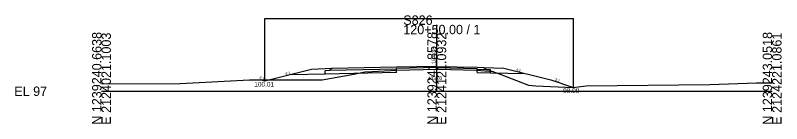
# Model space of a CAD drawing. Extents: x 2119282 to 2119710, y 1215030 to 1220057.
# Drawn here: x 2119381.9 to 2119610.4, y 1219030.1 to 1219062.5 of the extents above; entities that cross this region are included whole.
import ezdxf

# ---------------------------------------------------------------- set-up
doc = ezdxf.new("R2010")
doc.units = 0
for name, color, linetype in [('XS_CELL', 7, 'Continuous'), ('XS_M_DITCH', 7, 'Continuous'), ('XS_P_FINISHED_GRADE', 7, 'Continuous'), ('XS_P_FINISHED_GRADE_ELEV_TX', 7, 'Continuous'), ('XS_P_SUBGRADE_GRANULAR', 7, 'Continuous'), ('XS_P_SUBGRADE_PAVEMENT', 7, 'Continuous'), ('XS_P_TX_DCH', 7, 'Continuous'), ('XS_P_TX_FS_BS', 7, 'Continuous'), ('XS_X_GROUND', 7, 'Continuous'), ('XS_X_GROUND_TX', 7, 'Continuous')]:
    doc.layers.add(name, color=color, linetype=linetype)

msp = doc.modelspace()

# ---------------------------------------------------------------- linework, layer by layer
at = {"layer": 'XS_CELL'}
for p, q in [((2119507.6, 1219039.8), (2119507.6, 1219059.61)), ((2119407.6, 1219039.8), (2119507.6, 1219039.8)), ((2119507.6, 1219039.8), (2119607.6, 1219039.8))]:
    msp.add_line(p, q, dxfattribs=at)
at = {"layer": 'XS_M_DITCH'}
for p, q in [((2119456.27, 1219042.82), (2119456.27, 1219061.47)), ((2119456.27, 1219061.47), (2119548.41, 1219061.47)), ((2119548.41, 1219040.89), (2119548.41, 1219061.47))]:
    msp.add_line(p, q, dxfattribs=at)
at = {"layer": 'XS_P_FINISHED_GRADE'}
for p, q in [((2119470.27, 1219046.32), (2119456.27, 1219042.82)), ((2119476.27, 1219046.56), (2119470.27, 1219046.32)), ((2119495.6, 1219046.94), (2119476.27, 1219046.56)), ((2119507.6, 1219047.18), (2119495.6, 1219046.94)), ((2119507.6, 1219047.18), (2119519.6, 1219046.94)), ((2119519.6, 1219046.94), (2119521.6, 1219046.9)), ((2119521.6, 1219046.9), (2119527.6, 1219046.66)), ((2119527.6, 1219046.66), (2119541.6, 1219043.16)), ((2119456.27, 1219042.82), (2119455.08, 1219043.21)), ((2119541.6, 1219043.16), (2119548.41, 1219040.89))]:
    msp.add_line(p, q, dxfattribs=at)
at = {"layer": 'XS_P_SUBGRADE_GRANULAR'}
for p, q in [((2119475.62, 1219045.96), (2119474.27, 1219045.91)), ((2119474.27, 1219044.93), (2119474.27, 1219045.91)), ((2119495.6, 1219045.36), (2119495.61, 1219046.36)), ((2119519.6, 1219045.36), (2119519.59, 1219046.36)), ((2119522.26, 1219046.31), (2119523.6, 1219046.25)), ((2119523.6, 1219045.28), (2119523.6, 1219046.25)), ((2119474.27, 1219044.93), (2119463.91, 1219044.72)), ((2119495.6, 1219045.36), (2119474.27, 1219044.93)), ((2119519.6, 1219045.36), (2119523.6, 1219045.28)), ((2119523.6, 1219045.28), (2119533.97, 1219045.07))]:
    msp.add_line(p, q, dxfattribs=at)
at = {"layer": 'XS_P_SUBGRADE_PAVEMENT'}
for p, q in [((2119495.61, 1219046.36), (2119475.62, 1219045.96)), ((2119475.77, 1219046.21), (2119475.62, 1219045.96)), ((2119476.27, 1219046.56), (2119475.77, 1219046.21)), ((2119507.6, 1219046.85), (2119495.61, 1219046.61)), ((2119495.61, 1219046.36), (2119495.61, 1219046.61)), ((2119507.6, 1219046.85), (2119519.6, 1219046.61)), ((2119519.59, 1219046.36), (2119519.6, 1219046.61)), ((2119519.59, 1219046.36), (2119522.26, 1219046.31)), ((2119521.6, 1219046.9), (2119522.11, 1219046.56)), ((2119522.11, 1219046.56), (2119522.26, 1219046.31))]:
    msp.add_line(p, q, dxfattribs=at)
at = {"layer": 'XS_X_GROUND'}
for p, q in [((2119482.84, 1219044.92), (2119486.18, 1219045.56)), ((2119486.18, 1219045.56), (2119488.35, 1219045.66)), ((2119488.35, 1219045.66), (2119495.62, 1219046.06)), ((2119495.62, 1219046.06), (2119507.6, 1219046.4)), ((2119507.6, 1219046.4), (2119507.91, 1219046.39)), ((2119507.91, 1219046.39), (2119519.39, 1219046.04)), ((2119519.39, 1219046.04), (2119523.23, 1219045.82)), ((2119523.23, 1219045.82), (2119524, 1219045.76)), ((2119524, 1219045.76), (2119526.48, 1219044.89)), ((2119431.09, 1219042.13), (2119451.76, 1219043.19)), ((2119451.76, 1219043.19), (2119452.73, 1219043.23)), ((2119452.73, 1219043.23), (2119453.13, 1219043.21)), ((2119453.13, 1219043.21), (2119473.4, 1219043.23)), ((2119473.4, 1219043.23), (2119482.84, 1219044.92)), ((2119526.48, 1219044.89), (2119534.96, 1219041.56)), ((2119407.62, 1219041.98), (2119431.09, 1219042.13)), ((2119534.96, 1219041.56), (2119537.16, 1219041.41)), ((2119537.16, 1219041.41), (2119548.19, 1219040.86)), ((2119548.19, 1219040.86), (2119552.17, 1219041.45)), ((2119552.17, 1219041.45), (2119588.97, 1219041.78)), ((2119588.97, 1219041.78), (2119602.94, 1219042.3)), ((2119602.94, 1219042.3), (2119607.62, 1219042.27))]:
    msp.add_line(p, q, dxfattribs=at)

# ---------------------------------------------------------------- texts
at = {"layer": 'XS_CELL'}
for s, p in [('S826', (2119497.6, 1219059.61)), ('120+50.00 / 1', (2119497.6, 1219056.81)), ('EL 97', (2119381.6, 1219038.4))]:
    msp.add_text(s, height=2.8, dxfattribs=at).set_placement(p)
for s, p in [('N 1239240.6638', (2119407.6, 1219029.8)), ('E 2124021.1003', (2119410.4, 1219029.8)), ('N 1239241.8578', (2119507.6, 1219029.8)), ('E 2124121.0932', (2119510.4, 1219029.8)), ('N 1239243.0518', (2119607.6, 1219029.8)), ('E 2124221.0861', (2119610.4, 1219029.8))]:
    msp.add_text(s, height=2.8, rotation=90, dxfattribs=at).set_placement(p)
at = {"layer": 'XS_P_FINISHED_GRADE_ELEV_TX'}
msp.add_text('104.38', height=1.25, rotation=90, dxfattribs=at).set_placement((2119507.3, 1219047.85))
at = {"layer": 'XS_P_TX_DCH'}
for s, p in [('100.01', (2119453.16, 1219041.16)), ('98.09', (2119545.27, 1219039.26))]:
    msp.add_text(s, height=1.4, dxfattribs=at).set_placement(p)
at = {"layer": 'XS_P_TX_FS_BS'}
for s, rotation, p in [('4:1', 14.0362, (2119462.5, 1219044.6)), ('4:1', 345.9638, (2119531.11, 1219045.96)), ('3:1', 341.5651, (2119454.59, 1219043.62)), ('3:1', 341.5651, (2119542.71, 1219042.94))]:
    msp.add_text(s, height=0.8, rotation=rotation, dxfattribs=at).set_placement(p)
at = {"layer": 'XS_X_GROUND_TX'}
msp.add_text('103.60', height=1, dxfattribs=at).set_placement((2119504.96, 1219043.18))

doc.saveas('drawing.dxf')
